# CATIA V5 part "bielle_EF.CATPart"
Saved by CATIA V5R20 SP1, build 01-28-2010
Part number: bielle_EF
Bounding box of the stored display mesh (mm): x 18.462 to 34.772, y 25 to 35, z 58.705 to 87.679
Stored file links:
  C:\Users\Matthieu\Desktop\IAO_2012_mcamard_Catia\bielle_EF.CATPart
  C:\Users\Matthieu\Desktop\IAO_Artobolevsky\Artobolevsky_786.CATProduct
  C:\Users\Matthieu\Desktop\IAO_2012_mcamard_Catia\bielle_F.CATPart
  C:\Users\Matthieu\Desktop\IAO_2012_mcamard_Catia\piece_EA.CATPart
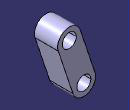
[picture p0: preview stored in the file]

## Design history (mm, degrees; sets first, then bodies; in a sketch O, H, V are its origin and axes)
Set1
  Plane1: linked copy from another document
  Point1 "F": linked copy from another document
  Point2 "E": linked copy from another document
Body1 (main body)
  Sketch1 on Plane1, origin (0, 0, 0), H (-1, 0, 0), V (0, 0, 1)
    construction line L1 (-23.4547, 63.705) -> (-29.7792, 82.6787)
    point P1 (-23.4547, 63.705)
    point P2 (-29.7792, 82.6787)
    line L2 (-28.1981, 62.1239) -> (-34.5227, 81.0975)
    line L3 (-25.0358, 84.2598) -> (-18.7113, 65.2862)
    arc A1 centre (-29.7792, 82.6787) radius 5 from (-34.5227, 81.0975) to (-25.0358, 84.2598) cw
    arc A2 centre (-23.4547, 63.705) radius 5 from (-18.7113, 65.2862) to (-28.1981, 62.1239) cw
    circle A3 centre (-29.7792, 82.6787) radius 3
    circle A4 centre (-23.4547, 63.705) radius 3
    reference projected point E1 (-29.7792, 82.6787) from Point1
    reference projected point E2 (-23.4547, 63.705) from Point2
    distance L1 L2 = 5
    tangency: A1 L2, A2 L2, A1 L3, A2 L3
    coincidence: E1 P2, P1 E2
  Pad1: profile Sketch1, direction (0, 1, 0), length 35, opposite side length -25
